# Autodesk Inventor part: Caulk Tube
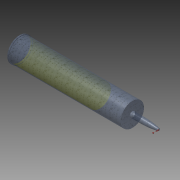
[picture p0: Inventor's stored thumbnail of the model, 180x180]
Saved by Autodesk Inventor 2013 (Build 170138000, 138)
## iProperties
Created: 2009-03
Part Number: Caulk Tube
Document SubType Name: Modeling
Designer: tangg
Density: 3.18 g/cm^3
Material: Silicon Nitride
Mass: 657.694 g
Surface Area: 779.569 cm^2
Volume: 206.822 cm^3
Author: tangg
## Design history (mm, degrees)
sketch "Sketch1"
  geometry: L1 (0.01, 26.745)-(-252.99, 26.745); L2 (-255.99, 26.745)-(-255.99, 0.245); L3 (-255.99, 0.245)-(0.01, 0.245); L4 (0.01, 0.245)-(0.01, 26.745); L5 (0.01, 0.245)-(60.01, 0.245); L6 (60.01, 0.245)-(60.01, 2.745); L7 (-252.99, 26.745)-(-252.99, 27.799); L8 (-252.99, 27.799)-(-255.99, 27.799); L9 (-255.99, 27.799)-(-255.99, 26.745); 4 further points
  constraints: 18 end point, 3 parallel, 3 perpendicular, 1 horizontal, 1 point on line, 4 other
  dimensions: "d25" = 26.5 distance between parallel lines of L3 L1; "d26" = 256 distance between parallel lines of L2 L4; "d27" = 60 distance between parallel lines of L4 L6; "d28" = 32 distance from line of L4 point (32.01, 6.016); "d29" = 6.5 distance of point (0, 0) point (0.01, 6.5); "d30" = 2.5 distance of L5.end L6.end; "d33" = 3 distance between parallel lines of L9 L7
revolve "Revolution1" sketch "Sketch1" stored, may be unused: angle "d17" = 90 deg
sketch "Sketch2"
  geometry: C1 r 26.5 at (0, 0); C2 r 25.5 at (0, 0); 1 further point
  constraints: 2 centre point, 1 concentric
  dimensions: "d18" = 1 radial gap between concentric circles of C2 C1
extrude "Extrusion1" cut sketch "Sketch2" distance "d19" = 182; taper "d20" = 0 deg
sketch "Sketch3"
  geometry: L1 (60.161, 0)-(60.161, -7.769); 4 further points
  constraints: 2 end point, 1 vertical, 5 other
revolve "Revolution2" sketch "Sketch3" stored, may be unused: angle "d31" = 90 deg
sketch "Sketch4"
  geometry: L1 (59.994, -10.28)-(59.994, -13.757); 3 further points
  constraints: 2 end point, 1 vertical, 4 other
revolve "Revolution3" sketch "Sketch4" stored, may be unused: angle "d32" = 90 deg
body "Solid1"
